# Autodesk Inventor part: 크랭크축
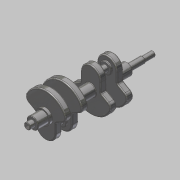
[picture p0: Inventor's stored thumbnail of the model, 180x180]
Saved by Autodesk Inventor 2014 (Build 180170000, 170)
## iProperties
Created: 2017-03
Part Number: 크랭크축
Material: 강철, 탄소
Document SubType Name: Modeling
Designer: mduedu
Density: 7.87 g/cm^3
Mass: 1840.77 g
Surface Area: 500.249 cm^2
Volume: 233.897 cm^3
Appearance: 반광택
Author: mduedu
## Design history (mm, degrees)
sketch "스케치1" dims "d5" = 57
  geometry: L1 (-19, 21.243)-(-19, 3.243); L2 (-19, 3.243)-(-40.023, -8.895); L3 (19, 21.243)-(19, 3.243); L4 (0, 21.243)-(0, -41); L5 (19, 3.243)-(40.023, -8.895); C1 r 6 at (0, 0); C2 r 13.5 at (0, 0); A1 r 41 centre (0, 0) between (-40.023, -8.895) and (0, -41); A2 r 41 centre (0, 0) between (0, -41) and (40.023, -8.895); A3 r 19 centre (0, 21.243) between (19, 21.243) and (0, 40.243); A4 r 19 centre (0, 21.243) between (0, 40.243) and (-19, 21.243); 3 further points
  constraints: 10 end point, 8 point on circle, 6 centre point, 5 coincident, 3 symmetric about line, 2 point on line, 1 parallel, 1 tangent, 1 vertical, 1 vertical alignment, 5 other
  dimensions: "d0" = 12 diameter of C1; "d1" = 27 diameter of C2; "d2" = 18 distance of L1.start L1.end; "d3" = 120 deg angle of L2 L1; "d4" = 41 radius of A1; "d6" = 19 radius of A4
extrude "돌출1" new body sketch "스케치1" distance "d7" = 12; taper "d8" = 0 deg
extrude "돌출2" join sketch "스케치1" distance "d9" = 5; taper "d10" = 0 deg
extrude "돌출3" join sketch "스케치1" distance "d11" = 75; taper "d12" = 0 deg
sketch "스케치2"
  geometry: C1 r 11 at (0, 21.243); C2 r 6 at (0, 21.243); A1 r 19 centre (0, 21.243) between (19, 21.243) and (-19, 21.243) reference; 1 further point
  constraints: 2 centre point, 2 coincident
  dimensions: "d13" = 22 diameter of C1; "d14" = 12 diameter of C2
extrude "돌출4" join sketch "스케치2" distance "d15" = 3; taper "d16" = 0 deg
extrude "돌출5" join sketch "스케치2" distance "d17" = 16; taper "d18" = 0 deg
fillet "모깎기1" dims "d19" = 3, "d20" = 10
fillet "모깎기2" dims "d21" = 2
sketch "스케치3"
  geometry: C1 r 11 at (0, 0); 1 further point
  constraints: 1 centre point, 1 coincident
  dimensions: "d22" = 22 diameter of C1
extrude "돌출6" join sketch "스케치3" distance "d23" = 21; taper "d24" = 0 deg
sketch "스케치4"
  geometry: C1 r 6 at (0, 0) reference; C2 r 5 at (0, 0); 1 further point
  constraints: 1 centre point
  dimensions: "d25" = 1 radial gap between concentric circles of C1 C2
extrude "돌출7" cut sketch "스케치4" distance "d26" = 20; taper "d27" = 0 deg
node "작업 평면1"
sketch "스케치5"
  geometry: L1 (-5, 0)-(5, 0) reference; L2 (-1.5, 0)-(1.5, 0); L3 (1.5, 0)-(1.5, 8.5); L4 (-1.5, 8.5)-(-1.5, 0); A1 r 1.5 centre (0, 8.5) between (1.5, 8.5) and (-1.5, 8.5); 1 further point
  constraints: 6 end point, 2 point on circle, 2 tangent, 1 centre point, 1 horizontal, 1 parallel, 1 perpendicular, 1 point on line, 1 vertical alignment
  dimensions: "d28" = 3 distance between parallel lines of L3 L4; "d30" = 10 dimension on A1 L1
extrude "돌출8" cut sketch "스케치5" distance "d31" = 1.8; taper "d32" = 0 deg
chamfer "모따기1" distance "d33" = 1; stored, may be unused: second distance "d34" = 2, angle "d35" = 45 deg
chamfer "모따기2" distance "d36" = 1; stored, may be unused: second distance "d37" = 2, angle "d38" = 45 deg
node "작업 평면2"
sketch "스케치6"
  geometry: C1 r 11 at (0, 0) reference; C2 r 11 at (0, 0) reference; 1 further point
extrude "돌출9" join sketch "스케치6" distance "d39" = 42; taper "d40" = 0 deg
sketch "스케치7" dims "d46" = 57
  geometry: L1 (-19, -21.243)-(-19, -3.243); L2 (19, -21.243)-(19, -3.243); L3 (-19, -3.243)-(-40.023, 8.895); L4 (19, -3.243)-(40.023, 8.895); L5 (0, -21.243)-(0, 41); C1 r 13.5 at (0, 0); C2 r 6 at (0, 0); A1 r 19 centre (0, -21.243) between (0, -40.243) and (19, -21.243); A2 r 19 centre (0, -21.243) between (-19, -21.243) and (0, -40.243); A3 r 41 centre (0, 0) between (0, 41) and (-40.023, 8.895); A4 r 41 centre (0, 0) between (40.023, 8.895) and (0, 41); 3 further points
  constraints: 10 end point, 8 point on circle, 6 centre point, 5 coincident, 3 symmetric about line, 2 point on line, 1 parallel, 1 tangent, 1 vertical, 5 other
  dimensions: "d41" = 12 diameter of C2; "d42" = 27 diameter of C1; "d43" = 18 distance of L2.start L2.end; "d44" = 120 deg angle of L4 L2; "d45" = 41 radius of A4; "d47" = 19 radius of A1
extrude "돌출10" join sketch "스케치7" distance "d48" = 12; taper "d49" = 0 deg
sketch "스케치8"
  geometry: C1 r 11 at (0, -21.243); C2 r 6 at (0, -21.243); A1 r 19 centre (0, -21.243) between (-19, -21.243) and (19, -21.243) reference; 1 further point
  constraints: 2 centre point, 2 coincident
  dimensions: "d50" = 22 diameter of C1; "d51" = 12 diameter of C2
extrude "돌출11" join sketch "스케치8" distance "d52" = 3; taper "d53" = 0 deg
extrude "돌출12" join sketch "스케치8" distance "d54" = 16; taper "d55" = 0 deg
fillet "모깎기3" dims "d56" = 3, "d57" = 10
fillet "모깎기4" dims "d58" = 2
chamfer "모따기3" distance "d59" = 1; stored, may be unused: second distance "d60" = 2, angle "d61" = 45 deg
node "작업 평면3"
fillet "모깎기5" dims "d62" = 1
sketch "스케치9"
  geometry: C1 r 13.5 at (0, 0) reference; 1 further point
extrude "돌출13" join sketch "스케치9" distance "d63" = 5; taper "d64" = 0 deg
sketch "스케치10"
  geometry: C1 r 6 at (0, 0) reference; 1 further point
extrude "돌출14" join sketch "스케치10" distance "d65" = 30; taper "d66" = 0 deg
sketch "스케치11"
  geometry: C1 r 11 at (0, 0); 1 further point
  constraints: 1 centre point, 1 coincident
  dimensions: "d67" = 22 diameter of C1
extrude "돌출15" join sketch "스케치11" distance "d68" = 20; taper "d69" = 0 deg
chamfer "모따기4" distance "d70" = 1; stored, may be unused: second distance "d71" = 2, angle "d72" = 45 deg
chamfer "모따기5" distance "d75" = 0.7; stored, may be unused: second distance "d76" = 2, angle "d77" = 30 deg
fillet "모깎기6" dims "d78" = 0.3
node "솔리드1"
mirror "대칭1"
mirror "대칭2"
node "투영된 루프1"
